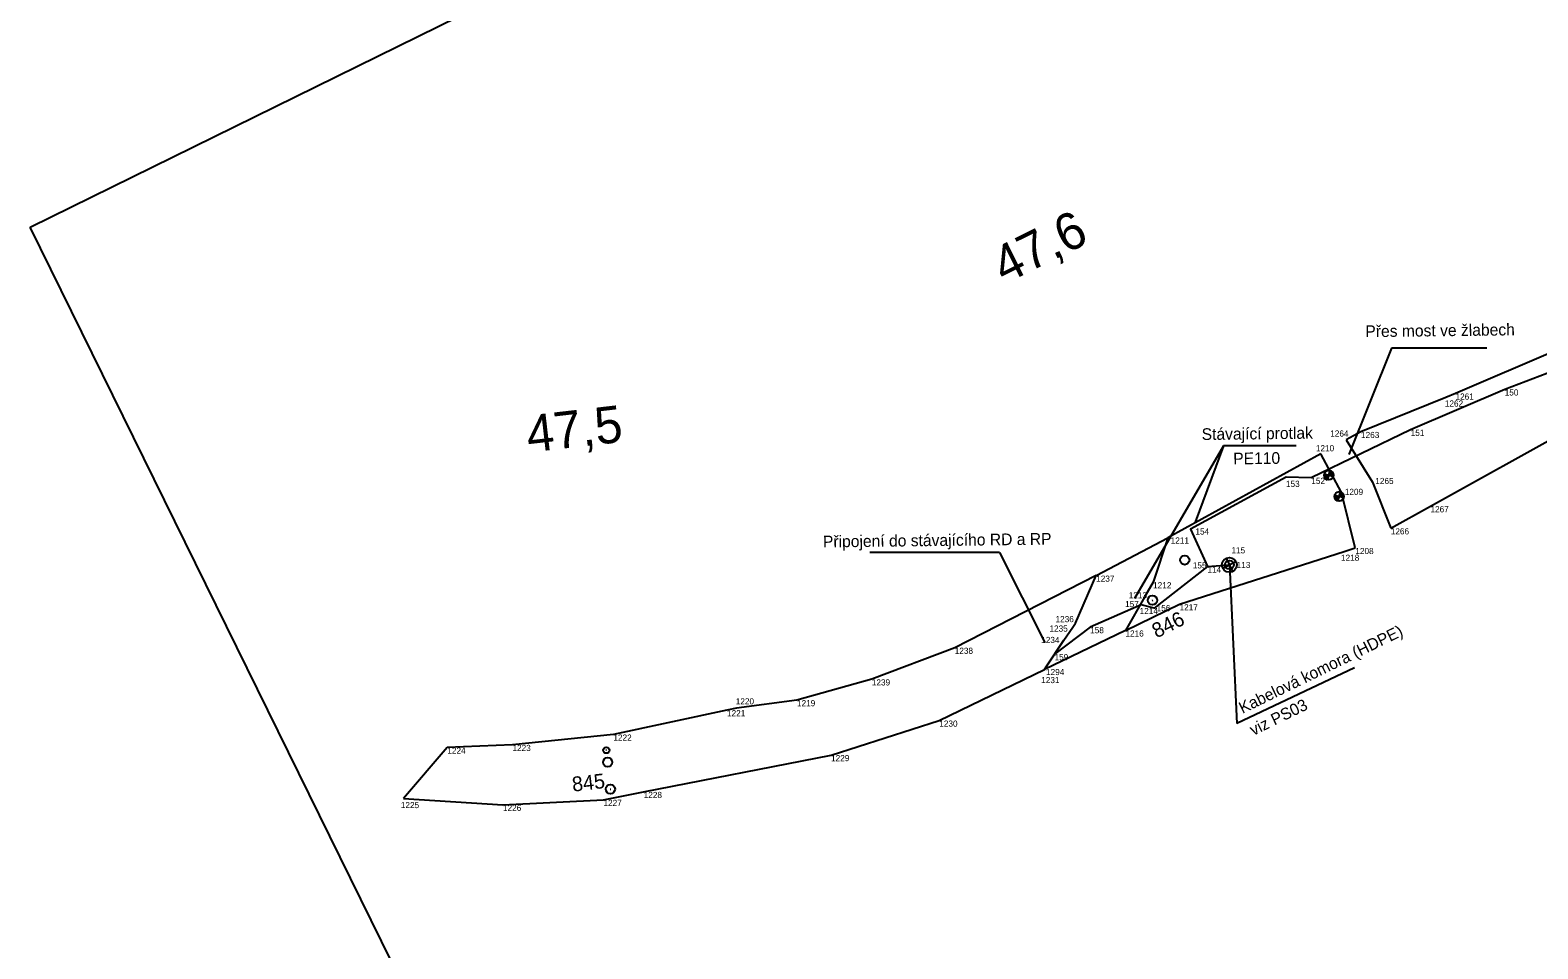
# Model space of a CAD drawing. Extents: x -679938 to -678300, y -1007495 to -1006487.
# Drawn here: x -679938.1 to -679693.1, y -1007345.9 to -1007196.7 of the extents above; entities that cross this region are included whole.
import ezdxf

# ---------------------------------------------------------------- set-up
doc = ezdxf.new("R2010")
doc.units = 0
for name, color, linetype in [('ramy - Sekce lichá', 7, 'Continuous'), ('Schéma kabelů', 7, 'Continuous'), ('SSZT nové - lomové body', 7, 'Continuous'), ('SSZT_nové', 7, 'Continuous'), ('Stávající ŽBP', 7, 'Continuous'), ('SŽDC', 7, 'Continuous'), ('SŽDC - body', 7, 'Continuous'), ('Trvalý zábor', 7, 'Continuous'), ('Vrstva 7', 7, 'Continuous')]:
    doc.layers.add(name, color=color, linetype=linetype)

msp = doc.modelspace()

# ---------------------------------------------------------------- linework, layer by layer
at = {"layer": 'ramy - Sekce lichá'}
for p, q in [((-679938.06, -1007228.7), (-679749.65, -1007135.95)), ((-679806.88, -1007495.16), (-679938.06, -1007228.7))]:
    msp.add_line(p, q, dxfattribs=at)
at = {"layer": 'Schéma kabelů'}
for p, q in [((-679744.3, -1007284.07), (-679742.14, -1007283)), ((-679743.76, -1007282.46), (-679742.68, -1007284.61))]:
    msp.add_line(p, q, dxfattribs=at)
for radius in [1.2, 0.714]:
    msp.add_circle((-679743.22, -1007283.54), radius, dxfattribs=at)
at = {"layer": 'SSZT nové - lomové body'}
for p, q in [((-679698.48, -1007255.03), (-679698.48, -1007255.03)), ((-679713.76, -1007261.59), (-679713.76, -1007261.59)), ((-679734.01, -1007269.32), (-679734.01, -1007269.32)), ((-679729.9, -1007269.39), (-679729.9, -1007269.39)), ((-679749.53, -1007277.73), (-679749.53, -1007277.73)), ((-679746.78, -1007283.82), (-679746.78, -1007283.82)), ((-679746.78, -1007283.82), (-679746.78, -1007283.82)), ((-679743.22, -1007283.54), (-679743.22, -1007283.54)), ((-679743.22, -1007283.54), (-679743.22, -1007283.54)), ((-679757.54, -1007290.05), (-679757.54, -1007290.05)), ((-679755.45, -1007290.57), (-679755.45, -1007290.57)), ((-679765.84, -1007293.65), (-679765.84, -1007293.65)), ((-679771.62, -1007298.04), (-679771.62, -1007298.04))]:
    msp.add_line(p, q, dxfattribs=at)
at = {"layer": 'SSZT_nové'}
for p, q in [((-679716.87, -1007248.34), (-679723.83, -1007265.6)), ((-679701.41, -1007248.34), (-679716.87, -1007248.34)), ((-679744.18, -1007264.22), (-679758.61, -1007288.98)), ((-679744.18, -1007264.22), (-679748.76, -1007276.61)), ((-679732.38, -1007264.22), (-679744.18, -1007264.22)), ((-679780.54, -1007281.52), (-679801.65, -1007281.52)), ((-679780.54, -1007281.52), (-679773.18, -1007296.13)), ((-679746.78, -1007283.82), (-679743.22, -1007283.54)), ((-679743.22, -1007283.54), (-679741.98, -1007309.31)), ((-679722.89, -1007300.29), (-679741.98, -1007309.31))]:
    msp.add_line(p, q, dxfattribs=at)
msp.add_lwpolyline([(-679506.94, -1007197.49), (-679535.13, -1007216.77), (-679557.73, -1007227.22), (-679581.18, -1007235.29), (-679605.83, -1007240.38), (-679630.65, -1007243.66), (-679644.83, -1007245.85), (-679645.68, -1007240.3), (-679660.24, -1007242.83), (-679665.36, -1007242.83), (-679680.25, -1007248.11), (-679698.48, -1007255.03), (-679713.76, -1007261.59), (-679729.9, -1007269.39), (-679734.01, -1007269.32), (-679749.53, -1007277.73), (-679746.78, -1007283.82), (-679755.45, -1007290.57), (-679757.54, -1007290.05), (-679765.84, -1007293.65), (-679771.62, -1007298.04)], dxfattribs=at)
at = {"layer": 'Stávající ŽBP'}
for p, q in [((-679727.8, -1007268.73), (-679727.07, -1007268.98)), ((-679727.55, -1007268.81), (-679727.74, -1007269.36)), ((-679727.27, -1007268.91), (-679727.5, -1007269.61)), ((-679727.07, -1007268.98), (-679727.32, -1007269.7)), ((-679727.07, -1007268.98), (-679726.83, -1007268.25)), ((-679726.35, -1007269.23), (-679727.07, -1007268.98)), ((-679726.65, -1007268.34), (-679726.89, -1007269.04)), ((-679726.42, -1007268.58), (-679726.6, -1007269.14)), ((-679725.38, -1007272.41), (-679725.14, -1007271.68)), ((-679724.96, -1007271.77), (-679725.2, -1007272.47)), ((-679724.73, -1007272.02), (-679724.91, -1007272.57)), ((-679726.11, -1007272.16), (-679725.38, -1007272.41)), ((-679725.86, -1007272.25), (-679726.05, -1007272.79)), ((-679725.58, -1007272.34), (-679725.81, -1007273.04)), ((-679725.38, -1007272.41), (-679725.63, -1007273.13)), ((-679724.66, -1007272.66), (-679725.38, -1007272.41)), ((-679755.76, -1007289.31), (-679755.67, -1007289.26)), ((-679843.84, -1007319.98), (-679843.74, -1007319.96))]:
    msp.add_line(p, q, dxfattribs=at)
for centre, radius in [((-679727.07, -1007268.98), 0.764), ((-679725.38, -1007272.41), 0.764), ((-679755.72, -1007289.29), 0.756), ((-679843.79, -1007319.97), 0.756)]:
    msp.add_circle(centre, radius, dxfattribs=at)
for centre, start, end in [((-679727.07, -1007268.98), 161.4711, 251.3646), ((-679727.07, -1007268.98), 341.0203, 71.3383), ((-679725.38, -1007272.41), 341.0203, 71.3383), ((-679725.38, -1007272.41), 161.4711, 251.3646)]:
    msp.add_arc(centre, 0.765, start, end, dxfattribs=at)
at = {"layer": 'SŽDC'}
for p, q in [((-679689.89, -1007248.62), (-679706.47, -1007255.7)), ((-679708.06, -1007256.34), (-679721.83, -1007261.94)), ((-679710.54, -1007274), (-679677.41, -1007255.58)), ((-679706.47, -1007255.7), (-679708.06, -1007256.34)), ((-679721.83, -1007261.94), (-679724.22, -1007263.25)), ((-679724.22, -1007263.25), (-679719.95, -1007270.12)), ((-679728.36, -1007265.52), (-679753.24, -1007279.15)), ((-679725, -1007271.78), (-679728.36, -1007265.52)), ((-679722.75, -1007280.79), (-679725, -1007271.78)), ((-679719.95, -1007270.12), (-679716.99, -1007277.59)), ((-679716.99, -1007277.59), (-679710.54, -1007274)), ((-679753.24, -1007279.15), (-679755.61, -1007286.35)), ((-679751.31, -1007289.93), (-679724.57, -1007281.37)), ((-679724.57, -1007281.37), (-679722.75, -1007280.79)), ((-679764.86, -1007285.28), (-679787.84, -1007297)), ((-679768.23, -1007293), (-679764.86, -1007285.28)), ((-679755.61, -1007286.35), (-679756.95, -1007288.69)), ((-679757.01, -1007288.8), (-679760.1, -1007294.19)), ((-679756.95, -1007288.69), (-679757.01, -1007288.8)), ((-679756.95, -1007288.69), (-679756.95, -1007288.69)), ((-679760.1, -1007294.19), (-679751.31, -1007289.93)), ((-679770.09, -1007295.79), (-679768.67, -1007293.66)), ((-679768.67, -1007293.66), (-679768.23, -1007293)), ((-679772.86, -1007299.94), (-679770.09, -1007295.79)), ((-679787.84, -1007297), (-679801.31, -1007302.13)), ((-679790.35, -1007308.83), (-679773.27, -1007300.56)), ((-679773.27, -1007300.56), (-679772.86, -1007299.94)), ((-679772.86, -1007299.94), (-679772.86, -1007299.94)), ((-679801.31, -1007302.13), (-679813.47, -1007305.51)), ((-679813.47, -1007305.51), (-679823.27, -1007306.8)), ((-679824.84, -1007307.14), (-679843.3, -1007311.1)), ((-679823.27, -1007306.8), (-679824.84, -1007307.14)), ((-679807.93, -1007314.43), (-679790.35, -1007308.83)), ((-679843.3, -1007311.1), (-679859.7, -1007312.78)), ((-679870.28, -1007313.22), (-679877.41, -1007321.47)), ((-679859.7, -1007312.78), (-679870.28, -1007313.22)), ((-679838.38, -1007320.42), (-679807.93, -1007314.43)), ((-679844.91, -1007321.71), (-679838.38, -1007320.42)), ((-679877.41, -1007321.47), (-679861.24, -1007322.51)), ((-679861.24, -1007322.51), (-679844.91, -1007321.71))]:
    msp.add_line(p, q, dxfattribs=at)
at = {"layer": 'SŽDC - body'}
for p, q in [((-679708.06, -1007256.34), (-679708.06, -1007256.34)), ((-679706.47, -1007255.7), (-679706.47, -1007255.7)), ((-679721.83, -1007261.94), (-679721.83, -1007261.94)), ((-679724.22, -1007263.25), (-679724.22, -1007263.25)), ((-679728.36, -1007265.52), (-679728.36, -1007265.52)), ((-679725, -1007271.78), (-679725, -1007271.78)), ((-679719.95, -1007270.12), (-679719.95, -1007270.12)), ((-679710.54, -1007274), (-679710.54, -1007274)), ((-679753.24, -1007279.15), (-679753.24, -1007279.15)), ((-679716.99, -1007277.59), (-679716.99, -1007277.59)), ((-679724.57, -1007281.37), (-679724.57, -1007281.37)), ((-679722.75, -1007280.79), (-679722.75, -1007280.79)), ((-679764.86, -1007285.28), (-679764.86, -1007285.28)), ((-679755.61, -1007286.35), (-679755.61, -1007286.35)), ((-679757.01, -1007288.8), (-679757.01, -1007288.8)), ((-679756.95, -1007288.69), (-679756.95, -1007288.69)), ((-679756.95, -1007288.69), (-679756.95, -1007288.69)), ((-679751.31, -1007289.93), (-679751.31, -1007289.93)), ((-679768.67, -1007293.66), (-679768.67, -1007293.66)), ((-679768.23, -1007293), (-679768.23, -1007293)), ((-679760.1, -1007294.19), (-679760.1, -1007294.19)), ((-679770.09, -1007295.79), (-679770.09, -1007295.79)), ((-679787.84, -1007297), (-679787.84, -1007297)), ((-679773.27, -1007300.56), (-679773.27, -1007300.56)), ((-679772.86, -1007299.94), (-679772.86, -1007299.94)), ((-679772.86, -1007299.94), (-679772.86, -1007299.94)), ((-679772.86, -1007299.94), (-679772.86, -1007299.94)), ((-679801.31, -1007302.13), (-679801.31, -1007302.13)), ((-679813.47, -1007305.51), (-679813.47, -1007305.51)), ((-679824.84, -1007307.14), (-679824.84, -1007307.14)), ((-679823.27, -1007306.8), (-679823.27, -1007306.8)), ((-679790.35, -1007308.83), (-679790.35, -1007308.83)), ((-679843.3, -1007311.1), (-679843.3, -1007311.1)), ((-679870.28, -1007313.22), (-679870.28, -1007313.22)), ((-679859.7, -1007312.78), (-679859.7, -1007312.78)), ((-679807.93, -1007314.43), (-679807.93, -1007314.43)), ((-679838.38, -1007320.42), (-679838.38, -1007320.42)), ((-679877.41, -1007321.47), (-679877.41, -1007321.47)), ((-679861.24, -1007322.51), (-679861.24, -1007322.51)), ((-679844.91, -1007321.71), (-679844.91, -1007321.71))]:
    msp.add_line(p, q, dxfattribs=at)
at = {"layer": 'Trvalý zábor'}
for p, q in [((-679764.86, -1007285.28), (-679753.24, -1007279.15)), ((-679760.1, -1007294.19), (-679773.27, -1007300.56))]:
    msp.add_line(p, q, dxfattribs=at)
at = {"layer": 'Vrstva 7'}
msp.add_line((-679844.4, -1007313.65), (-679844.5, -1007313.66), dxfattribs=at)
for centre, radius in [((-679750.47, -1007282.76), 0.75), ((-679844.45, -1007313.65), 0.5), ((-679844.23, -1007315.6), 0.75)]:
    msp.add_circle(centre, radius, dxfattribs=at)

# ---------------------------------------------------------------- texts
at = {"layer": 'SSZT nové - lomové body'}
for s, p in [('150', (-679698.48, -1007256.03)), ('151', (-679713.76, -1007262.59)), ('152', (-679729.9, -1007270.39)), ('153', (-679734.02, -1007270.88)), ('154', (-679748.73, -1007278.61)), ('115', (-679742.88, -1007281.67)), ('155', (-679749.16, -1007284.12)), ('114', (-679746.78, -1007284.82)), ('113', (-679742.04, -1007284.06)), ('157', (-679760.16, -1007290.41)), ('156', (-679755.03, -1007291.07)), ('158', (-679765.84, -1007294.65)), ('159', (-679771.62, -1007299.04))]:
    msp.add_text(s, height=1, dxfattribs=at).set_placement(p)
at = {"layer": 'SSZT_nové'}
for s, rotation, p in [('Přes most ve žlabech', 0.7098, (-679721.11, -1007246.55)), ('Stávající protlak', 0.7098, (-679747.71, -1007263.26)), ('PE110', 0.7098, (-679742.58, -1007267.22)), ('Připojení do stávajícího RD a RP', 0.7098, (-679809.24, -1007280.71)), ('Kabelová komora (HDPE)', 25.9995, (-679741.09, -1007307.76)), ('viz PS03', 25.9995, (-679739.32, -1007311.33))]:
    msp.add_text(s, height=1.9, rotation=rotation, dxfattribs=at).set_placement(p)
at = {"layer": 'Stávající ŽBP'}
for s, rotation, p in [('846', 26.3578, (-679755.05, -1007295.5)), ('845', 6.5339, (-679849.88, -1007320.39))]:
    msp.add_text(s, height=2.4, rotation=rotation, dxfattribs=at).set_placement(p)
at = {"layer": 'SŽDC - body'}
for s, p in [('1262', (-679708.21, -1007257.83)), ('1261', (-679706.47, -1007256.7)), ('1264', (-679726.83, -1007262.7)), ('1263', (-679721.83, -1007262.94)), ('1210', (-679729.16, -1007265.09)), ('1265', (-679719.51, -1007270.41)), ('1209', (-679724.46, -1007272.18)), ('1267', (-679710.54, -1007275)), ('1211', (-679752.75, -1007280.08)), ('1266', (-679716.99, -1007278.59)), ('1218', (-679725.08, -1007282.88)), ('1208', (-679722.75, -1007281.79)), ('1237', (-679764.86, -1007286.28)), ('1212', (-679755.61, -1007287.35)), ('1213', (-679759.57, -1007288.98)), ('1214', (-679757.8, -1007291.54)), ('1217', (-679751.31, -1007290.93)), ('1235', (-679772.45, -1007294.39)), ('1236', (-679771.46, -1007292.85)), ('1216', (-679760.1, -1007295.19)), ('1234', (-679773.79, -1007296.24)), ('1238', (-679787.84, -1007298)), ('1294', (-679773.01, -1007301.45)), ('1239', (-679801.31, -1007303.13)), ('1231', (-679773.79, -1007302.75)), ('1220', (-679823.42, -1007306.21)), ('1219', (-679813.47, -1007306.51)), ('1221', (-679824.84, -1007308.14)), ('1230', (-679790.35, -1007309.83)), ('1222', (-679843.3, -1007312.1)), ('1224', (-679870.28, -1007314.22)), ('1223', (-679859.7, -1007313.78)), ('1229', (-679807.93, -1007315.43)), ('1228', (-679838.38, -1007321.42)), ('1225', (-679877.83, -1007323.06)), ('1226', (-679861.24, -1007323.51)), ('1227', (-679844.91, -1007322.71))]:
    msp.add_text(s, height=1, dxfattribs=at).set_placement(p)
at = {"layer": 'Vrstva 7'}
for s, rotation, p in [('47,6', 26.3597, (-679779.78, -1007238.01)), ('47,5', 6.5339, (-679857.08, -1007265.3))]:
    msp.add_text(s, height=6, rotation=rotation, dxfattribs=at).set_placement(p)

doc.saveas('drawing.dxf')
